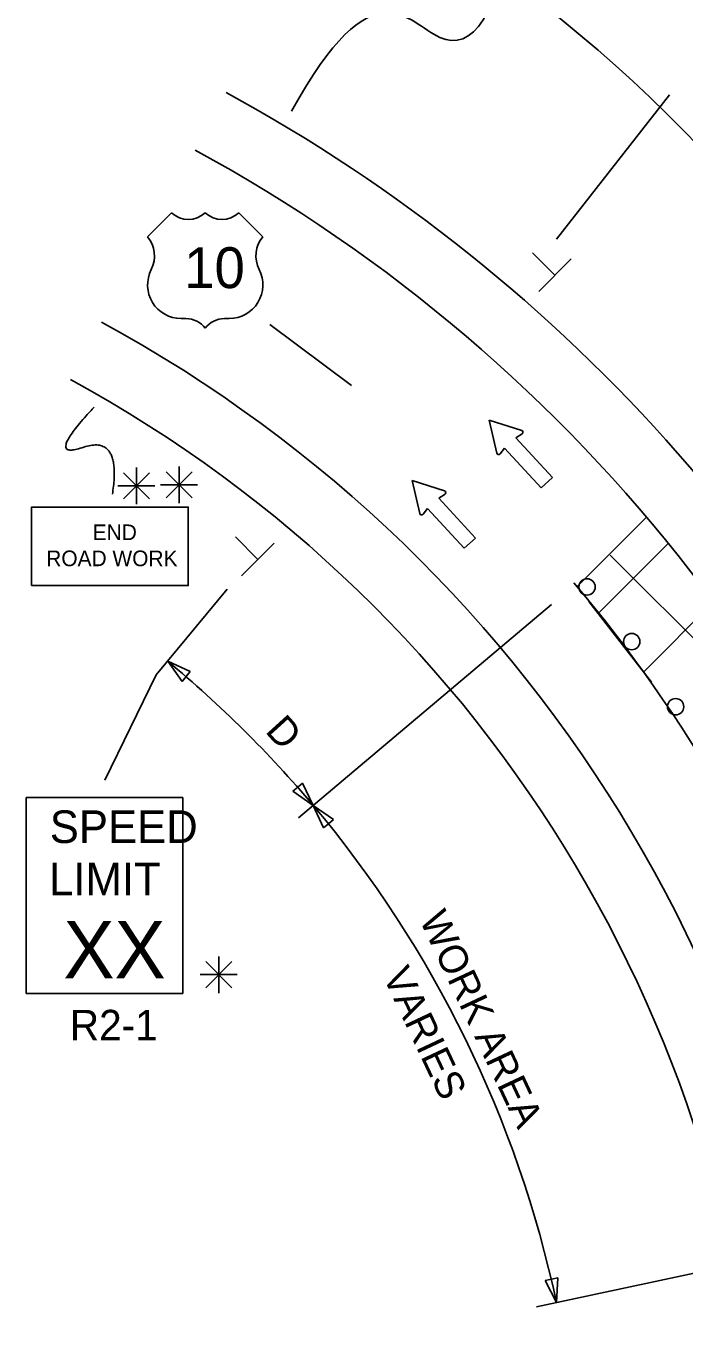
# Model space of a CAD drawing. Extents: x 16728 to 19508, y 5553 to 7079.
# Drawn here: x 16727.7 to 16889.1, y 6484.5 to 6806.3 of the extents above; entities that cross this region are included whole.
import ezdxf

# ---------------------------------------------------------------- set-up
doc = ezdxf.new("R2010")
doc.units = 0
for name, color, linetype in [('ALI_LEGAL_EX', 7, 'Continuous'), ('MT_SCRATCH_LEVEL_A', 7, 'Continuous'), ('MT_SCRATCH_LEVEL_E', 7, 'Continuous'), ('PAVT_EDGE_EX', 7, 'Continuous'), ('TRAFFIC_SIGNS_PR', 7, 'Continuous'), ('TYPICAL_EX', 7, 'Continuous'), ('TYPICAL_TEXT_DIMEN_PR', 7, 'Continuous')]:
    doc.layers.add(name, color=color, linetype=linetype)

msp = doc.modelspace()

# ---------------------------------------------------------------- linework, layer by layer
at = {"layer": 'ALI_LEGAL_EX'}
for points in [[(16807.35, 6718.27), (16787.33, 6733.25)], [(16880.88, 6645.61), (16865.54, 6665.36)]]:
    msp.add_lwpolyline(points, dxfattribs=at)
for centre, end in [((16629.65, 6525.15), 57.2958), ((16583.82, 6435.06), 40.1909)]:
    msp.add_arc(centre, 364, 0, end, dxfattribs=at)
at = {"layer": 'MT_SCRATCH_LEVEL_A'}
for p, q in [((16862.64, 6669.01), (16879.71, 6686.08)), ((16867.96, 6662.56), (16885.03, 6679.63)), ((16921.62, 6625.93), (16870.81, 6676.74)), ((16878.96, 6648.1), (16896.13, 6665.28))]:
    msp.add_line(p, q, dxfattribs=at)
at = {"layer": 'MT_SCRATCH_LEVEL_E'}
for p, q in [((16849.09, 6707.3), (16841.13, 6709.83)), ((16841.13, 6709.83), (16843, 6701.71)), ((16847.67, 6705.5), (16849.19, 6706.47)), ((16856.64, 6695.73), (16847.67, 6705.5)), ((16843.82, 6701.53), (16844.92, 6702.97)), ((16844.92, 6702.97), (16853.88, 6693.2)), ((16830.19, 6692.5), (16822.24, 6695.03)), ((16822.24, 6695.03), (16824.11, 6686.92)), ((16853.88, 6693.2), (16856.64, 6695.73)), ((16828.78, 6690.7), (16830.3, 6691.67)), ((16837.74, 6680.94), (16828.78, 6690.7)), ((16824.92, 6686.74), (16826.02, 6688.17)), ((16826.02, 6688.17), (16834.99, 6678.41)), ((16834.99, 6678.41), (16837.74, 6680.94))]:
    msp.add_line(p, q, dxfattribs=at)
for centre, start, end in [((16848.94, 6706.86), 302.594, 72.331), ((16843.46, 6701.82), 192.9827, 322.5217), ((16830.04, 6692.06), 302.594, 72.331), ((16824.56, 6687.03), 192.9827, 322.5217)]:
    msp.add_arc(centre, 0.463, start, end, dxfattribs=at)
at = {"layer": 'PAVT_EDGE_EX'}
for radius, start in [(404, 21.0961), (388, 14.0482), (340, 0), (324, 0)]:
    msp.add_arc((16583.82, 6435.06), radius, start, 61.4862, dxfattribs=at)
at = {"layer": 'TRAFFIC_SIGNS_PR'}
for p, q in [((16727.67, 6617.34), (16766.07, 6617.34)), ((16727.67, 6569.34), (16727.67, 6617.34)), ((16766.07, 6569.34), (16766.07, 6617.34)), ((16727.67, 6569.34), (16766.07, 6569.34))]:
    msp.add_line(p, q, dxfattribs=at)
msp.add_lwpolyline([(16728.96, 6669.3), (16767.36, 6669.3), (16767.36, 6688.5), (16728.96, 6688.5)], close=True, dxfattribs=at)
for centre in [(16865.11, 6668.96), (16876.07, 6655.56), (16886.82, 6639.61)]:
    msp.add_circle(centre, 2, dxfattribs=at)
at = {"layer": 'TYPICAL_EX'}
for p, q in [((16757.38, 6754.75), (16763.27, 6760.64)), ((16785.67, 6754.75), (16779.78, 6760.64)), ((16765.62, 6734.69), (16766.8, 6734.69)), ((16777.43, 6734.69), (16776.25, 6734.69))]:
    msp.add_line(p, q, dxfattribs=at)
for centre, radius, start, end in [((16767.4, 6764.94), 5.96, 226.1404, 313.8596), ((16775.65, 6764.94), 5.96, 226.1404, 313.8596), ((16751.79, 6750.03), 7.31, 333.0977, 40.1936), ((16791.26, 6750.03), 7.31, 139.8064, 206.9023), ((16765.64, 6742.93), 8.24, 152.6698, 269.9013), ((16777.41, 6742.93), 8.24, 270.0987, 27.3302), ((16766.82, 6728.78), 5.91, 37.1038, 90.1385), ((16776.23, 6728.78), 5.91, 89.8615, 142.8962)]:
    msp.add_arc(centre, radius, start, end, dxfattribs=at)
at = {"layer": 'TYPICAL_TEXT_DIMEN_PR'}
for p, q in [((16857.64, 6754.19), (16885.3, 6789.55)), ((16857.24, 6745.35), (16851.73, 6750.84)), ((16861.21, 6749.33), (16853.27, 6741.36)), ((16751.49, 6696.91), (16757.87, 6690.53)), ((16757.87, 6696.91), (16751.49, 6690.53)), ((16754.68, 6693.72), (16754.68, 6698.18)), ((16761.96, 6697.17), (16768.33, 6690.79)), ((16768.33, 6697.17), (16761.96, 6690.79)), ((16765.15, 6693.98), (16765.15, 6698.44)), ((16754.68, 6693.72), (16750.15, 6693.72)), ((16754.68, 6693.72), (16757.87, 6693.72)), ((16754.68, 6693.72), (16759.16, 6693.72)), ((16754.68, 6693.72), (16754.68, 6689.22)), ((16765.15, 6693.98), (16760.61, 6693.98)), ((16765.15, 6693.98), (16768.33, 6693.98)), ((16765.15, 6693.98), (16769.62, 6693.98)), ((16765.15, 6693.98), (16765.15, 6689.48)), ((16784.43, 6675.69), (16778.92, 6681.19)), ((16788.4, 6679.68), (16780.46, 6671.71)), ((16759.53, 6647.38), (16776.91, 6668.37)), ((16759.53, 6647.38), (16776.91, 6668.37)), ((16794.39, 6612.39), (16856.44, 6664.65)), ((16765.85, 6645.82), (16762.34, 6650.77)), ((16762.34, 6650.77), (16767.85, 6648.24)), ((16759.53, 6647.38), (16746.92, 6621.6)), ((16766.85, 6647.03), (16765.85, 6645.82)), ((16767.85, 6648.24), (16766.85, 6647.03)), ((16793.01, 6618.89), (16794.21, 6619.9)), ((16794.21, 6619.9), (16795.41, 6620.91)), ((16795.41, 6620.91), (16797.99, 6615.42)), ((16797.99, 6615.42), (16793.01, 6618.89)), ((16800.56, 6609.92), (16797.99, 6615.42)), ((16797.99, 6615.42), (16802.97, 6611.95)), ((16801.76, 6610.94), (16800.56, 6609.92)), ((16802.97, 6611.95), (16801.76, 6610.94)), ((16774.85, 6573.96), (16774.85, 6578.41)), ((16771.67, 6577.15), (16778.04, 6570.77)), ((16778.04, 6577.15), (16771.67, 6570.77)), ((16774.85, 6573.96), (16770.32, 6573.96)), ((16774.85, 6573.96), (16778.04, 6573.96)), ((16774.85, 6573.96), (16779.33, 6573.96)), ((16774.85, 6573.96), (16774.85, 6569.46)), ((16852.73, 6492.58), (16936.83, 6510.57)), ((16854.86, 6499.03), (16856.4, 6499.36)), ((16857.62, 6493.63), (16854.86, 6499.03)), ((16856.4, 6499.36), (16857.93, 6499.69)), ((16857.93, 6499.69), (16857.62, 6493.63))]:
    msp.add_line(p, q, dxfattribs=at)
for start, end in [(40.102, 50.3886), (12.0744, 40.102)]:
    msp.add_arc((16583.82, 6435.06), 280, start, end, dxfattribs=at)
for points, degree in [([(16792.71, 6785.53), (16812.75, 6822.09), (16829.8, 6792), (16843.76, 6808.28), (16846.76, 6833.99)], 3), ([(16744.31, 6713.02), (16731.94, 6699.84), (16751.15, 6706.43), (16748.78, 6691.66)], 2)]:
    msp.add_open_spline(points, degree=degree, dxfattribs=at)

# ---------------------------------------------------------------- texts
at = {"layer": 'TRAFFIC_SIGNS_PR'}
for s, height, p in [('END', 3.831, (16743.96, 6680.43)), ('ROAD WORK', 3.831, (16732.57, 6674.04)), ('SPEED', 8, (16733.43, 6606.21)), ('LIMIT', 8, (16733.27, 6593.41)), ('XX', 14.031, (16736.78, 6573.1)), ('R2-1', 7.44, (16738.34, 6557.9))]:
    msp.add_text(s, height=height, dxfattribs=at).set_placement(p)
at = {"layer": 'TYPICAL_EX'}
msp.add_text('10', height=10, dxfattribs=at).set_placement((16766.37, 6742.17))
at = {"layer": 'TYPICAL_TEXT_DIMEN_PR'}
for s, rotation, p in [('D', 312.2189, (16786.01, 6633.51)), ('WORK AREA', 295.1762, (16823.91, 6587.55)), ('VARIES', 295.1762, (16814.91, 6573.77))]:
    msp.add_text(s, height=7, rotation=rotation, dxfattribs=at).set_placement(p)

doc.saveas('drawing.dxf')
